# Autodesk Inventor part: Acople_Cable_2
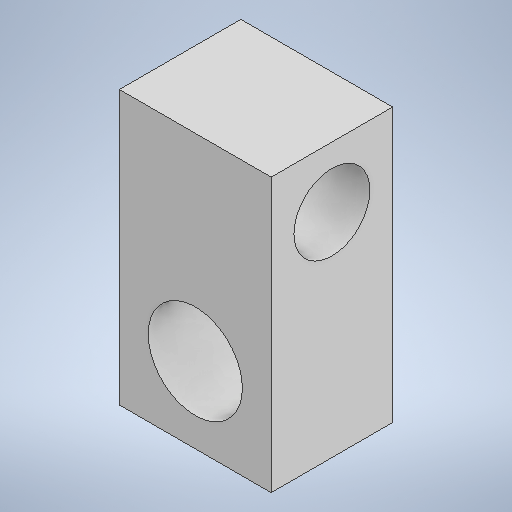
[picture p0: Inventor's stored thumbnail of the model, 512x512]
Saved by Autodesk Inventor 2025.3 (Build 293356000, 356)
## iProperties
Created: 2025-12
Part Number: Acople_Cable_2
Material: Genérico
Document SubType Name: Modeling
Designer: Dell
Density: 1 g/cm^3
Appearance: Valor por defecto
Author: Dell
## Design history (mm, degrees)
sketch "Boceto1"
  geometry: L1 (-5, 5)-(5, 5); L2 (5, 5)-(5, -5); L3 (5, -5)-(-5, -5); L4 (-5, -5)-(-5, 5); L5 (-5, 5)-(5, -5); L6 (5, 5)-(-5, -5); C1 r 3.1 at (0, 0); 1 further point
  constraints: 12 end point, 2 midpoint, 2 parallel, 1 centre point, 1 coincident, 1 horizontal, 1 perpendicular
  dimensions: "d0" = 6.2 diameter of C1; "d1" = 10 distance of L2.end L3.end; "d2" = 10 distance of L1.end L2.end
extrude "Extrusión1" new body sketch "Boceto1" distance "d3" = 8; taper "d4" = 0 deg
sketch "Boceto2"
  geometry: L1 (0, 0)-(10, 0) reference; L2 (0, -8)-(10, -8) reference; L3 (0, 0)-(10, 0); L4 (10, 0)-(10, -8); L5 (10, -8)-(0, -8); L6 (0, -8)-(0, 0); 3 further points
  constraints: 8 end point, 2 parallel, 1 horizontal, 1 perpendicular
extrude "Extrusión2" join sketch "Boceto2" distance "d5" = 8; taper "d6" = 0 deg
sketch "Boceto3"
  geometry: L1 (0, 0)-(8, 0) reference; L2 (0, 0)-(0, 18) reference; L3 (8, 0)-(8, 18) reference; C1 r 2.5 at (4, 14); 1 further point
  constraints: 1 centre point
  dimensions: "d8" = 5 diameter of C1
extrude "Extrusión3" cut sketch "Boceto3" distance "d9" = 10; taper "d10" = 0 deg
node "Sólido1"
